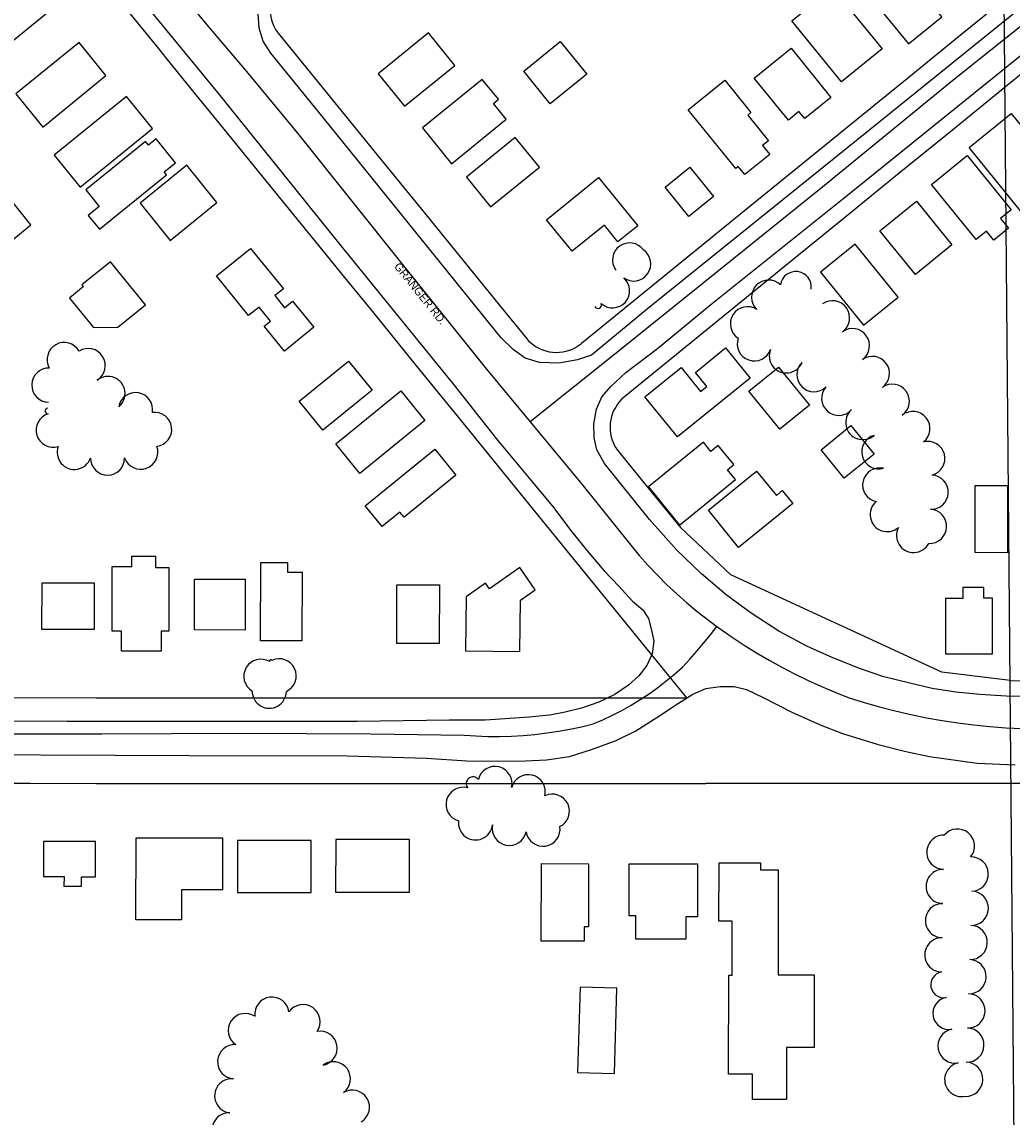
# Model space of a CAD drawing. Extents: x -2233 to 187241, y 4582 to 150524.
# Drawn here: x 117426 to 118005, y 58341 to 58982 of the extents above; entities that cross this region are included whole.
import ezdxf

# ---------------------------------------------------------------- set-up
doc = ezdxf.new("R2010")
doc.units = 0
for name, color, linetype in [('BLDG', 7, 'Continuous'), ('GE_X_CL_2000', 7, 'Continuous'), ('GRID', 7, 'Continuous'), ('ROAD', 7, 'Continuous'), ('ROAD-NAME', 7, 'Continuous'), ('RW_X_Fee_RW', 7, 'Continuous'), ('TREES', 7, 'Continuous')]:
    doc.layers.add(name, color=color, linetype=linetype)

msp = doc.modelspace()

# ---------------------------------------------------------------- linework, layer by layer
at = {"layer": 'BLDG'}
for points in [[(117395.02, 58990.22), (117415.02, 58965.58), (117444.79, 58989.74), (117424.79, 59014.39)], [(117964.24, 58984.46), (117944.79, 59008.41), (117939.69, 59004.27), (117935.94, 59008.88), (117921.59, 58997.23), (117944.79, 58968.66)], [(117900.3, 59001.43), (117929.27, 58965.75), (117905.49, 58946.45), (117876.53, 58982.14)], [(117650.03, 58932.2), (117679.51, 58956.13), (117664.15, 58975.05), (117634.68, 58951.12)], [(117438.57, 58920.08), (117475.58, 58950.13), (117459.84, 58969.51), (117422.83, 58939.47)], [(117756.63, 58950.98), (117735.31, 58933.67), (117719.8, 58952.79), (117741.12, 58970.09)], [(117876.05, 58966.16), (117899.37, 58937.42), (117884.02, 58924.96), (117880.7, 58929.05), (117874.51, 58924.03), (117854.51, 58948.67)], [(117677.55, 58898.63), (117709.57, 58924.63), (117702.03, 58933.92), (117704.95, 58936.29), (117695.54, 58947.88), (117660.59, 58919.51)], [(117837.29, 58947.38), (117852.56, 58928.57), (117850.76, 58927.09), (117862.96, 58912.06), (117859.42, 58909.18), (117863.62, 58904.01), (117849.1, 58892.22), (117845.22, 58897), (117843.71, 58895.78), (117815.91, 58930.04)], [(117460.44, 58884.96), (117502.69, 58919.26), (117487.61, 58937.85), (117445.35, 58903.54)], [(118004.71, 58927.88), (118034.66, 58890.99), (118010.21, 58871.15), (117980.27, 58908.04)], [(117471.59, 58873.57), (117465.18, 58868.36), (117471.71, 58860.31), (117510.94, 58892.15), (117509.61, 58893.78), (117516.22, 58899.14), (117504.84, 58913.14), (117500.33, 58909.47), (117498.6, 58911.6), (117463.71, 58883.27)], [(117700.45, 58873.34), (117729, 58896.52), (117714.78, 58914.01), (117686.24, 58890.84)], [(117979.06, 58903.4), (118004.81, 58871.67), (117998.53, 58866.58), (118003.15, 58860.89), (117994.63, 58853.96), (117990.38, 58859.19), (117984.36, 58854.29), (117958.22, 58886.49)], [(117495.48, 58875.47), (117513.11, 58853.75), (117540.47, 58875.96), (117522.84, 58897.68)], [(117816.92, 58896.52), (117830.76, 58879.47), (117816.39, 58867.82), (117802.55, 58884.86)], [(117786.46, 58862.37), (117774.87, 58852.95), (117766.91, 58862.75), (117748.03, 58847.41), (117733.03, 58865.9), (117763.5, 58890.64)], [(117393.23, 58874.18), (117414.05, 58848.53), (117431.72, 58862.86), (117410.9, 58888.51)], [(117949.31, 58876.73), (117970.11, 58851.11), (117948.78, 58833.79), (117927.99, 58859.42)], [(117938.61, 58820.64), (117913.52, 58851.56), (117893.31, 58835.16), (117918.41, 58804.25)], [(117560.1, 58849.14), (117579.26, 58825.55), (117574.29, 58821.5), (117580.02, 58814.44), (117584.66, 58818.2), (117597.01, 58802.99), (117579.86, 58789.07), (117568.05, 58803.62), (117571.75, 58806.61), (117565.07, 58814.82), (117558.98, 58809.87), (117540.21, 58833)], [(117461.54, 58827.88), (117462.45, 58826.76), (117454.25, 58820.11), (117468.18, 58802.94), (117482.42, 58803.08), (117498.58, 58816.2), (117478.15, 58841.36)], [(117811.75, 58779.52), (117823.17, 58765.46), (117826.81, 58768.4), (117820.11, 58776.66), (117837.79, 58791.01), (117852.17, 58773.31), (117809.77, 58738.88), (117790.67, 58762.41)], [(117631.21, 58766.28), (117602.39, 58742.89), (117588.58, 58759.9), (117617.4, 58783.29)], [(117868.64, 58779.75), (117886.77, 58757.42), (117869.48, 58743.39), (117851.34, 58765.71)], [(117662.03, 58748.47), (117623.95, 58717.55), (117609.87, 58734.88), (117647.96, 58765.8)], [(117924.61, 58728.86), (117907.19, 58714.71), (117893.67, 58731.39), (117911.08, 58745.52)], [(117810.81, 58687.42), (117843.52, 58713.99), (117838.86, 58719.73), (117842.57, 58722.74), (117833.47, 58733.94), (117829.2, 58730.47), (117824.89, 58735.79), (117792.73, 58709.69)], [(117680.09, 58716.53), (117649.86, 58691.99), (117647.45, 58694.95), (117636.99, 58686.46), (117627.1, 58698.64), (117667.79, 58731.68)], [(117827.77, 58696.06), (117855.91, 58718.91), (117867.46, 58704.69), (117870.94, 58707.52), (117877.04, 58700.01), (117845.41, 58674.33)], [(118002.53, 58710.46), (118002.5, 58671.24), (117983.66, 58671.25), (117983.68, 58710.47)], [(117490.61, 58663.22), (117490.61, 58669.22), (117504.54, 58669.21), (117504.54, 58662.55), (117512.27, 58662.54), (117512.26, 58625.33), (117507.88, 58625.34), (117507.88, 58613.7), (117484.58, 58613.71), (117484.59, 58625.28), (117479.18, 58625.29), (117479.19, 58663.22)], [(117581.63, 58665.54), (117581.63, 58659.85), (117590.17, 58659.85), (117590.15, 58619.67), (117565.99, 58619.68), (117566.02, 58665.56)], [(117717.55, 58613.53), (117717.86, 58643.49), (117726.51, 58649.55), (117717.48, 58662.48), (117699.68, 58650.04), (117697.36, 58653.35), (117686.05, 58645.44), (117685.71, 58613.86)], [(117438.17, 58653.65), (117468.62, 58653.63), (117468.61, 58626.27), (117438.15, 58626.29)], [(117556.99, 58655.84), (117556.97, 58626.01), (117527.35, 58626.04), (117527.37, 58655.85)], [(117670.46, 58652.37), (117670.43, 58618.17), (117645.56, 58618.19), (117645.59, 58652.38)], [(117993.89, 58612.01), (117993.91, 58644.68), (117988.84, 58644.68), (117988.84, 58650.87), (117976.55, 58650.88), (117976.55, 58644.46), (117966.28, 58644.46), (117966.26, 58612.03)], [(117543.66, 58504.57), (117543.63, 58474.09), (117519.7, 58474.1), (117519.68, 58456.57), (117493.1, 58456.6), (117493.14, 58504.62)], [(117438.95, 58481.94), (117451.03, 58481.92), (117451.01, 58476.37), (117461.23, 58476.36), (117461.25, 58481.67), (117469.37, 58481.66), (117469.39, 58502.36), (117438.97, 58502.38)], [(117552.5, 58472.6), (117595.52, 58472.56), (117595.55, 58503.01), (117552.53, 58503.04)], [(117609.82, 58472.8), (117652.98, 58472.77), (117653, 58503.59), (117609.85, 58503.62)], [(117757.71, 58489.43), (117757.68, 58452.56), (117755.04, 58452.57), (117755.03, 58444.14), (117730.07, 58444.16), (117730.1, 58489.45)], [(117821.3, 58489.35), (117821.28, 58458.32), (117814.5, 58458.34), (117814.49, 58445.28), (117785.27, 58445.31), (117785.28, 58458.91), (117781.45, 58458.92), (117781.47, 58489.38)], [(117858.17, 58489.98), (117858.18, 58485.87), (117868.49, 58485.87), (117868.43, 58424.42), (117889.56, 58424.41), (117889.52, 58382.04), (117873.42, 58382.06), (117873.4, 58351.5), (117853.6, 58351.51), (117853.61, 58366.36), (117839.56, 58366.38), (117839.61, 58424.24), (117841.59, 58424.24), (117841.63, 58455.85), (117833.93, 58455.86), (117833.96, 58490)], [(117752.74, 58417.32), (117751.31, 58367.34), (117772.79, 58366.73), (117774.23, 58416.69)]]:
    msp.add_lwpolyline(points, close=True, dxfattribs=at)
at = {"layer": 'GE_X_CL_2000'}
for points in [[(118208.24, 59140.93), (118184.21, 59120.21), (118112.61, 59061.61), (118079.68, 59034.86), (118052.29, 59014.32), (118016.81, 58984.17), (117970.73, 58947.26), (117895.63, 58885.94), (117816.71, 58822.32), (117767.99, 58783.23), (117723.54, 58747.76)], [(117527.76, 58987.99), (117536.75, 58977.28), (117557.79, 58952.57), (117587.53, 58916.55), (117649.41, 58838.84), (117698.09, 58778.46), (117723.54, 58747.76)], [(117723.54, 58747.76), (117753.75, 58711.3), (117782.31, 58675.57), (117787.34, 58669.56), (117792.55, 58663.72), (117797.93, 58658.03), (117803.49, 58652.5), (117809.2, 58647.14), (117815.07, 58641.96), (117821.12, 58636.93), (117832.67, 58628.16)], [(117377.69, 58565.26), (117473.13, 58565.39), (117554.56, 58565.7), (117630.31, 58565.42), (117684.99, 58564.51), (117691.88, 58564.08), (117698.78, 58563.86), (117705.69, 58563.84), (117712.59, 58564.03), (117719.48, 58564.42), (117726.35, 58565.02), (117733.21, 58565.83), (117740.04, 58566.84), (117746.83, 58568.05), (117753.59, 58569.47), (117760.29, 58571.09), (117766.02, 58573.54), (117771.66, 58576.19), (117777.2, 58579.05), (117782.63, 58582.1), (117787.94, 58585.36), (117793.13, 58588.8), (117798.2, 58592.43), (117803.13, 58596.24), (117807.91, 58600.23), (117812.55, 58604.39), (117816.79, 58608.98), (117820.92, 58613.67), (117824.95, 58618.43), (117828.87, 58623.27), (117832.67, 58628.16)], [(117832.67, 58628.16), (117841.63, 58621.84), (117848.7, 58617.19), (117855.88, 58612.72), (117863.18, 58608.43), (117870.59, 58604.33), (117878.1, 58600.43), (117885.71, 58596.72), (117893.41, 58593.21), (117901.2, 58589.9), (117909.48, 58586.63), (117918.83, 58583.69), (117927.83, 58581.12), (117936.89, 58578.77), (117946, 58576.66), (117955.17, 58574.78), (117964.38, 58573.13), (117973.63, 58571.73), (117982.91, 58570.55), (117992.23, 58569.62), (118001.56, 58568.93), (118011.17, 58568.46)]]:
    msp.add_lwpolyline(points, dxfattribs=at)
at = {"layer": 'GRID'}
msp.add_line((117990.78, 60113.41), (118014.32, 57415.73), dxfattribs=at)
at = {"layer": 'ROAD'}
for points in [[(118076.87, 59043.6), (117922.35, 58918.72), (117792.22, 58813.75), (117759.38, 58786.79), (117751.17, 58783.94), (117740.28, 58781.93), (117729.04, 58782.4), (117720.66, 58784.98), (117713.54, 58789.95), (117706.61, 58796.76), (117667.95, 58844.56), (117602.57, 58925.65), (117571.9, 58963.26), (117567.37, 58970.21), (117565.16, 58977.86), (117564.49, 58986.71), (117566.42, 58993.81), (117570.28, 59001.92), (117575.82, 59009.12), (117586.11, 59017.87), (117679.24, 59095.37), (117802.24, 59193.71), (117951.86, 59315.01), (118024.92, 59378.23)], [(117477.75, 59017.01), (117540.77, 58940.34), (117613.09, 58850.47), (117678.91, 58769.32), (117704.52, 58737.08), (117724.88, 58712.44), (117737.41, 58697.39), (117747.07, 58684.46), (117757.77, 58671.18), (117766.84, 58660.7), (117775.37, 58651.59), (117783.43, 58642.98), (117789.43, 58637.79), (117792.63, 58632.82), (117794.56, 58625.98), (117795.85, 58619.56), (117794.94, 58612.18), (117791.74, 58605.3), (117787.05, 58599.32), (117781.02, 58593.87), (117773.09, 58588.29), (117763.73, 58583.88), (117753.58, 58580.32), (117744.02, 58577.99), (117735.01, 58576.18), (117722.82, 58575.09), (117708.92, 58574.14), (117697.29, 58573.39), (117676.44, 58573.29), (117622.48, 58572.57), (117542.15, 58572.6), (117452.89, 58572.46), (117380.84, 58572.95)], [(118028.84, 58586.79), (118001.9, 58587.39), (117986.41, 58588.34), (117972.48, 58589.74), (117958.55, 58591.82), (117945.58, 58594.89), (117930.33, 58598.58), (117916.61, 58603.34), (117900.57, 58609.73), (117885.27, 58616.59), (117868.96, 58625.45), (117852.79, 58635.96), (117838.19, 58646.51), (117823.61, 58658.84), (117809.28, 58672.64), (117793.25, 58690.69), (117766.99, 58723.36), (117762.49, 58731.39), (117760.87, 58738.44), (117760.8, 58746.54), (117762.36, 58755.14), (117765.49, 58762.34), (117770.74, 58768.47), (117779.41, 58776.66), (117797.9, 58790.68), (117829.2, 58816.34), (117907.16, 58878.64), (118024.07, 58973.04)], [(117350.35, 58553.41), (117524.22, 58552.64), (117616.48, 58552.42), (117663.02, 58551.07), (117686.45, 58549.53), (117704.46, 58549.29), (117720.8, 58549.49), (117733.13, 58550.08), (117746.62, 58552.16), (117759.35, 58556.11), (117773.75, 58561.45), (117785.37, 58567.02), (117798.27, 58575.29), (117810.18, 58583.27), (117818.69, 58588.62), (117826.32, 58591.89), (117834.58, 58592.99), (117842.82, 58592.93), (117850.03, 58591.26), (117860.13, 58586.39), (117876.43, 58577.92), (117893.01, 58570.65), (117906.23, 58565.5), (117926.9, 58559.19), (117942.29, 58555.25), (117956.96, 58552.05), (117984.91, 58548.13), (118006.98, 58547.19)]]:
    msp.add_lwpolyline(points, dxfattribs=at)
at = {"layer": 'RW_X_Fee_RW'}
for p, q in [((117802.53, 58696.8), (117811.38, 58685.98)), ((117840.83, 58658.2), (117811.38, 58685.98)), ((117964.13, 58601.4), (117840.83, 58658.2)), ((118004.13, 58596.5), (117964.13, 58601.4)), ((118004.13, 58596.5), (118013.23, 58596.3)), ((117559.83, 58586.4), (117814.93, 58586.4)), ((118342.03, 58536.16), (117962.33, 58536.34))]:
    msp.add_line(p, q, dxfattribs=at)
for points in [[(118222.03, 59174.5), (118162.35, 59125.97), (118131.31, 59100.72), (118115.81, 59088.12), (118100.31, 59075.52), (118069.26, 59050.26), (118038.21, 59025.02), (118007.22, 58999.81), (117976.11, 58974.52), (117945.12, 58949.31), (117914.12, 58924.1), (117883.02, 58898.81), (117852.02, 58873.6), (117753.53, 58793.5)], [(118247.23, 59143.5), (118187.57, 59094.97), (118156.52, 59069.71), (118125.52, 59044.5), (118094.48, 59019.25), (118063.43, 58993.99), (118032.39, 58968.74), (118001.4, 58943.53), (117970.35, 58918.27), (117939.31, 58893.02), (117908.31, 58867.81), (117877.26, 58842.56), (117778.73, 58762.4)], [(117414.72, 59078.39), (117447.33, 59038.3), (117477.02, 59001.8), (117478.9, 58999.48), (117506.04, 58966.11), (117509.17, 58962.26), (117510.44, 58960.71), (117526.22, 58941.3), (117542.01, 58921.89), (117574.16, 58882.35), (117606.68, 58842.37), (117613.33, 58834.2)], [(117579.13, 59003.1), (117577.83, 59001.9), (117576.63, 59000.7), (117575.53, 58999.3), (117574.53, 58997.8), (117573.73, 58996.3), (117573.03, 58994.7), (117572.53, 58993), (117572.13, 58991.3), (117571.83, 58989.6), (117571.73, 58987.9), (117571.83, 58986.1), (117572.03, 58984.4), (117572.33, 58982.7), (117572.83, 58981), (117573.53, 58979.4), (117574.23, 58977.8), (117575.13, 58976.4), (117576.23, 58975)], [(117576.23, 58975), (117609.45, 58934.12), (117634.68, 58903.07), (117659.93, 58872)], [(117659.93, 58872), (117685.14, 58841.02), (117710.4, 58809.98), (117721.13, 58796.8)], [(117613.33, 58834.2), (117631.9, 58811.38), (117657.16, 58780.33), (117682.41, 58749.29), (117707.62, 58718.3), (117732.92, 58687.2), (117814.93, 58586.4)], [(117721.13, 58796.8), (117722.43, 58795.3), (117723.93, 58793.9), (117725.53, 58792.7), (117727.13, 58791.6), (117728.93, 58790.6), (117730.83, 58789.8), (117732.73, 58789.2), (117734.63, 58788.7), (117736.63, 58788.4), (117738.63, 58788.3), (117740.63, 58788.4), (117742.63, 58788.6), (117744.63, 58789), (117746.53, 58789.6), (117748.33, 58790.3), (117750.13, 58791.2), (117751.83, 58792.3), (117753.53, 58793.5)], [(117778.73, 58762.4), (117777.23, 58761.1), (117775.83, 58759.6), (117774.63, 58758.1), (117773.53, 58756.4), (117772.53, 58754.6), (117771.73, 58752.8), (117771.13, 58750.9), (117770.63, 58748.9), (117770.33, 58746.9), (117770.23, 58744.9), (117770.33, 58742.9), (117770.53, 58740.9), (117770.93, 58739), (117771.53, 58737), (117772.23, 58735.2), (117773.13, 58733.4), (117774.23, 58731.7), (117775.43, 58730.1)], [(117775.43, 58730.1), (117786.15, 58716.92), (117802.53, 58696.8)], [(117023.93, 58587.18), (117113.93, 58587.02), (117203.93, 58586.86), (117248.93, 58586.79), (117293.93, 58586.71), (117338.93, 58586.63), (117383.93, 58586.55), (117469.78, 58586.4)], [(117469.78, 58586.4), (117514.73, 58586.4), (117559.83, 58586.4)], [(117136.13, 58536.93), (117195.13, 58536.88), (117254.13, 58536.78), (117314.13, 58536.67), (117372.23, 58536.57), (117431.23, 58536.47), (117469.83, 58536.4)], [(117469.83, 58536.4), (117490.33, 58536.4), (117549.33, 58536.4), (117559.83, 58536.4)], [(117559.83, 58536.4), (117608.33, 58536.4), (117661.13, 58536.4), (117716.23, 58536.4), (117773.23, 58536.4), (117826.23, 58536.4)], [(117962.33, 58536.34), (117895.23, 58536.37), (117826.23, 58536.4)]]:
    msp.add_lwpolyline(points, dxfattribs=at)
at = {"layer": 'TREES'}
for centre, radius, start, end in [((117781.7, 58842.31), 10, 36.17391, 216.17391), ((117784.02, 58840.04), 10, 234.85716, 54.85716), ((117771.68, 58824.34), 10, 228.79975, 48.79975), ((117878.86, 58826.57), 9.05, 352.07864, 172.07864), ((117862.96, 58820.62), 10, 46.05677, 226.05677), ((117900.28, 58808.52), 10, 305.65644, 125.65644), ((117763.21, 58815.99), 2.05, 203.53344, 23.53344), ((117850.58, 58805.03), 10, 57.05344, 237.05344), ((117911.94, 58792.27), 10, 305.65644, 125.65644), ((117451.13, 58784.12), 10, 29.47579, 209.47579), ((117854.59, 58793.35), 10, 160.8015, 340.8015), ((117465.16, 58780.58), 10, 302.18511, 122.18511), ((117873.29, 58786.29), 10, 157.82317, 337.82317), ((117889.49, 58775.31), 10, 133.94001, 313.94001), ((117923.6, 58776.02), 10, 305.65644, 125.65644), ((117442.2, 58769.2), 10, 88.67616, 268.67616), ((117476.74, 58764.31), 10, 308.68914, 128.68914), ((117903.91, 58761.48), 10, 138.44919, 318.44919), ((117935.25, 58759.77), 10, 305.65644, 125.65644), ((117492.85, 58754.84), 10, 350.42393, 170.42393), ((117441.62, 58754.07), 1.67, 93.49978, 273.49978), ((117918, 58747.34), 10, 131.37362, 311.37362), ((117444.69, 58742.85), 10, 107.22811, 287.22811), ((117504.01, 58743.26), 10, 277.45534, 97.45534), ((117947.3, 58743.81), 10, 308.3998, 128.3998), ((117927.35, 58730.22), 10, 105.90009, 285.90009), ((117955.99, 58726.29), 10, 284.40012, 104.40012), ((117457.06, 58729.92), 10, 160.21543, 340.21543), ((117495.89, 58729.99), 10, 199.61258, 19.61258), ((117476.47, 58726.58), 10, 180.29523, 0.29523), ((117927.92, 58710.84), 10, 77.43485, 257.43485), ((117957.99, 58706.61), 10, 267.20787, 87.20787), ((117932.29, 58693.52), 10, 130.87258, 310.87258), ((117957.02, 58686.64), 10, 267.20787, 87.20787), ((117947.68, 58681.3), 10, 152.26251, 332.26251), ((117566.12, 58598.95), 10, 59.26424, 239.26424), ((117571.9, 58607.92), 0.759, 29.44784, 209.44784), ((117576.78, 58599.23), 10, 295.00773, 115.00773), ((117571.01, 58590.26), 10, 179.46262, 359.46262), ((117702.97, 58536.27), 10, 346.12891, 166.12891), ((117690.14, 58536.22), 3.97, 38.01456, 218.01456), ((117722.39, 58531.47), 10, 346.12891, 166.12891), ((117684.36, 58524.13), 10, 74.63587, 254.63587), ((117736.52, 58520.11), 10, 296.26971, 116.26971), ((117691.64, 58513.28), 10, 173.02753, 353.02753), ((117711.37, 58510.1), 10, 168.6774, 348.6774), ((117731.06, 58509.64), 10, 188.63469, 8.63469), ((117965.39, 58496.12), 10, 88.83791, 268.83791), ((117973.29, 58499.73), 10, 320.32993, 140.32993), ((117981.39, 58483.36), 10, 272.26602, 92.26602), ((117964.99, 58476.12), 10, 88.83791, 268.83791), ((117981.45, 58463.37), 10, 268.13368, 88.13368), ((117964.58, 58456.13), 10, 88.83791, 268.83791), ((117980.8, 58443.38), 10, 268.13368, 88.13368), ((117964.18, 58436.13), 10, 88.83791, 268.83791), ((117980.15, 58423.39), 10, 268.13368, 88.13368), ((117965.32, 58418.67), 7.58, 100.24204, 280.24204), ((117572.57, 58401.47), 10, 7.34643, 187.34643), ((117968.35, 58401.93), 9.43, 100.24204, 280.24204), ((117979.5, 58403.4), 10, 268.13368, 88.13368), ((117590.71, 58397.06), 10, 325.28826, 145.28826), ((117557.04, 58391.92), 10, 55.83375, 235.83375), ((117600.74, 58381.53), 10, 280.43604, 100.43604), ((117971.92, 58382.83), 10, 100.92486, 280.92486), ((117978.85, 58383.41), 10, 268.13368, 88.13368), ((117550.79, 58373.67), 10, 86.38216, 266.38216), ((117608.5, 58363.66), 10, 306.52875, 126.52875), ((117975.84, 58363.22), 10, 101.71073, 281.71073), ((117978.2, 58363.42), 10, 268.13368, 88.13368), ((117549.06, 58353.75), 10, 83.7044, 263.7044), ((117619.64, 58347.07), 10, 301.22899, 121.22899), ((117547.59, 58333.81), 10, 87.86191, 267.86191)]:
    msp.add_arc(centre, radius, start, end, dxfattribs=at)

# ---------------------------------------------------------------- texts
at = {"layer": 'ROAD-NAME'}
msp.add_text('GRANGER RD.', height=4.68, rotation=308.88622, dxfattribs=at).set_placement((117643.69, 58838.44))

doc.saveas('drawing.dxf')
